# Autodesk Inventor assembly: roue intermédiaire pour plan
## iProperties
Shininess: 64.0
Length Units: 11269
Angle Units: 11279
Time Units: 11290
Mass Units: 11283
Length Display Precision: 3
Angle Display Precision: 2
Compacted: True
Created: 2004-09
Part Number: roue intermédiaire pour plan
Document SubType Name: Assembly
Designer: Administrateur
Density: 0.0
Volumn: 0.0
Area: 0.0
PropertySet Name: Model Information
Control State: 0
Master: False
Checked Out: False
Author: Administrateur
